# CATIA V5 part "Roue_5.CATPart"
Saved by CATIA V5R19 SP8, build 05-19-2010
Part number: Roue_5
Nomenclature: 70_R5
Bounding box of the stored display mesh (mm): x -12.982 to 12.982, y -12.982 to 12.982, z 0 to 2
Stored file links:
  C:\Users\rphgr\Desktop\0_Tapis_TC520B_vitesse\Roue_5.CATPart
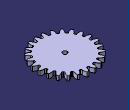
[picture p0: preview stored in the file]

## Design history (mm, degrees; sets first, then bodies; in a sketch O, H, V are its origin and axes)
External parameters (linked from other documents)
  External.Module = 1 mm
  External.Z = 24
  External.DiamPrimitif = 24 mm {= External.Module *External.Z}
  External.AnglePression = 20 deg
  External.x = 0
  External.DeportDenture = 0 mm {= External.x *External.Module}
  External.DiamBase = 22.5526 mm {= External.DiamPrimitif *cos(External.AnglePression )}
  External.DiamPied = 21.5 mm {= External.DiamPrimitif -2.5*External.Module +2*External.DeportDenture}
  External.DiamTete = 26 mm {= External.DiamPrimitif +2*External.Module +2*External.DeportDenture}
  External.PhiPrimitif = 0.854 deg {= atan((sin(External.ThetaPrimitif*1rad)-External.ThetaPrimitif*cos(External.ThetaPrimitif*1rad))/(cos(External.ThetaPrimitif*1rad)+External.ThetaPrimitif*sin(External.ThetaPrimitif*1rad)))}
  External.PhiTete = 3.0271 deg {= atan((sin(External.ThetaTete*1rad)-External.ThetaTete*cos(External.ThetaTete*1rad))/(cos(External.ThetaTete*1rad)+External.ThetaTete*sin(External.ThetaTete*1rad)))}
  External.PhiSymetrie = 3.75 deg {= 180*1 deg/(2*External.Z )}
  External.CongePied = 0.38 mm {= 0.38*External.Module}
  External.AlphaCopie = 15 deg {= 360*1 deg/External.Z}
  External.AlphaSymetrieCopie = 7.5 deg {= External.AlphaCopie /2}
  External.CoeffQualiteEngrenage = 7
  External.LargeurDenture = 2 mm
  External.ThetaPrimitif = 0.36397 {= sqrt(abs((External.DiamPrimitif*External.DiamPrimitif)/(External.DiamBase *External.DiamBase )-1))}
  External.ThetaTete = 0.573659 {= sqrt(abs((External.DiamTete*External.DiamTete)/(External.DiamBase *External.DiamBase )-1) )}
  External.Di = 23.2763 mm {= (External.DiamBase +External.DiamPrimitif )/2}
  External.Thetai = 0.255358 {= sqrt(abs((External.Di*External.Di)/(External.DiamBase*External.DiamBase)-1))}
  External.Phii = 0.3061 deg {= atan((sin(External.Thetai*1rad)-External.Thetai*cos(External.Thetai*1rad))/(cos(External.Thetai*1rad)+External.Thetai*sin(External.Thetai*1rad)))}
  External.Dj = 25 mm {= (External.DiamTete+External.DiamPrimitif)/2}
  External.Thetaj = 0.478344 {= sqrt(abs((External.Dj*External.Dj)/(External.DiamBase*External.DiamBase)-1))}
  External.Phij = 1.8433 deg {= atan((sin(External.Thetaj*1rad)-External.Thetaj*cos(External.Thetaj*1rad))/(cos(External.Thetaj*1rad)+External.Thetaj*sin(External.Thetaj*1rad)))}
  External.Dk = 22.9145 mm {= (External.Di+External.DiamBase)/2}
  External.Thetak = 0.179851 {= sqrt(abs((External.Dk*External.Dk)/(External.DiamBase*External.DiamBase)-1))}
  External.Phik = 0.109 deg {= atan((sin(External.Thetak*1rad)-External.Thetak*cos(External.Thetak*1rad))/(cos(External.Thetak*1rad)+External.Thetak*sin(External.Thetak*1rad)))}
  External.Dl = 23.6382 mm {= (External.DiamPrimitif+External.Di)/2}
  External.Thetal = 0.31398 {= sqrt(abs((External.Dl*External.Dl)/(External.DiamBase*External.DiamBase)-1))}
  External.Phil = 0.5585 deg {= atan((sin(External.Thetal*1rad)-External.Thetal*cos(External.Thetal*1rad))/(cos(External.Thetal*1rad)+External.Thetal*sin(External.Thetal*1rad)))}
  External.Dm = 24.5 mm {= (External.Dj+External.DiamPrimitif)/2}
  External.Thetam = 0.424444 {= sqrt(abs((External.Dm*External.Dm)/(External.DiamBase*External.DiamBase)-1))}
  External.Phim = 1.3203 deg {= atan((sin(External.Thetam*1rad)-External.Thetam*cos(External.Thetam*1rad))/(cos(External.Thetam*1rad)+External.Thetam*sin(External.Thetam*1rad)))}
  External.Dn = 25.5 mm {= (External.DiamTete+External.Dj)/2}
  External.Thetan = 0.527691 {= sqrt(abs((External.Dn*External.Dn)/(External.DiamBase*External.DiamBase)-1))}
  External.Phin = 2.4143 deg {= atan((sin(External.Thetan*1rad)-External.Thetan*cos(External.Thetan*1rad))/(cos(External.Thetan*1rad)+External.Thetan*sin(External.Thetan*1rad)))}
  External.DiametreAlesage = 2 mm
Body1 (main body)
  Sketch1 on xy-plane, origin (0, 0, 0), H (1, 0, 0), V (0, 1, 0)
    construction circle A1 centre (0, 0) radius 12
    construction circle A2 centre (0, 0) radius 11.2763
    construction circle A3 centre (0, 0) radius 10.75
    construction circle A4 centre (0, 0) radius 13
    point P1 (11.2763, 0)
    construction line L1 (11.2763, 0) -> (0, 0)
    point P2 (11.9987, 0.1788)
    construction line L2 (11.9987, 0.1788) -> (0, 0)
    point P3 (12.9819, 0.6865)
    construction line L3 (12.9819, 0.6865) -> (0, 0)
    construction line L4 (11.2763, 0) -> (11.2763, 3.9367)
    point P4 (11.2763, 0)
    point P6 (10.554, 0.1788)
    construction line L5 (12.9819, 0.6865) -> (11.9987, 0.1788)
    point P7 (12.4903, 0.4327)
    point P8 (10.0624, 0.4327)
    spline S1 through (10.0624, 0.4327) (10.554, 0.1788) (11.2763, 0) (11.4572, 0.0218) (11.638, 0.0622) (11.8185, 0.1152) (11.9987, 0.1788) (12.2467, 0.2823) (12.4935, 0.4021) (12.7387, 0.5371) (12.9819, 0.6865)
    construction line L6 (0, 0) -> (5.2574, 0.4234)
    spline S2 through (10.0019, 1.1831) (10.4466, 1.5123) (11.131, 1.8044) (11.3131, 1.8118) (11.498, 1.8009) (11.6847, 1.7775) (11.8727, 1.7435) (12.1341, 1.6811) (12.3969, 1.6023) (12.6605, 1.5083) (12.9244, 1.3997)
    arc A5 centre (11.1236, -0.3788) radius 0.38 from (11.147, 0.0005) to (10.7438, -0.3659) ccw
    point P11 (10.7438, -0.3659)
    arc A6 centre (0, 0) radius 13 from (12.9819, 0.6865) to (12.9244, 1.3997) ccw
    point P13 (12.9244, 1.3997)
    arc A7 centre (10.9196, 2.1539) radius 0.38 from (10.5468, 2.0804) to (11.0034, 1.7833) ccw
    point P15 (10.5468, 2.0804)
    construction line L7 (0, 0) -> (4.188, 0.8981)
    construction line L8 (0, 0) -> (5.1193, -0.259)
    point P19 (10.511, 2.2541)
    arc A8 centre (0, 0) radius 10.75 from (10.5468, 2.0804) to (10.511, 2.2541) ccw
    point P20 (10.7363, -0.5431)
    arc A9 centre (0, 0) radius 10.75 from (10.7363, -0.5431) to (10.7438, -0.3659) ccw
    line L9 (10.511, 2.2541) -> (0, 0)
    line L10 (10.7363, -0.5431) -> (0, 0)
    construction circle A10 centre (0, 0) radius 11.6382
    construction line L11 (0, 0) -> (2.5698, 0.0137)
    point P22 (11.638, 0.0622)
    construction circle A11 centre (0, 0) radius 12.5
    construction line L12 (0, 0) -> (4.017, 0.1293)
    point P24 (12.4935, 0.4021)
    point P25 (12.4935, 0.4021)
    point P26 (12.3969, 1.6023)
    point P27 (11.498, 1.8009)
    construction circle A12 centre (0, 0) radius 11.4572
    construction line L13 (0, 0) -> (48.2618, 0.0918)
    point P29 (11.3131, 1.8118)
    construction line L14 (0, 0) -> (63.772, 5.1354)
    point P31 (11.4572, 0.0218)
    construction circle A13 centre (0, 0) radius 11.8191
    construction line L15 (0, 0) -> (57.3607, 0.5591)
    point P33 (11.8185, 0.1152)
    point P34 (11.6847, 1.7775)
    construction circle A14 centre (0, 0) radius 12.25
    construction line L16 (0, 0) -> (65.6933, 1.5141)
    point P36 (12.2467, 0.2823)
    point P37 (12.1341, 1.6811)
    construction circle A15 centre (0, 0) radius 12.75
    axis line L17 (0, 0) -> (59.2983, 2.5001)
    point P39 (12.6605, 1.5083)
    point P40 (12.7387, 0.5371)
    point P42 (10.0624, 0.4327)
    point P43 (10.554, 0.1788)
    point P44 (11.2763, 0)
    point P45 (11.9987, 0.1788)
    point P46 (12.9819, 0.6865)
    point P47 (12.9244, 1.3997)
    point P48 (10.0019, 1.1831)
    point P49 (11.8727, 1.7435)
    point P50 (11.131, 1.8044)
    point P51 (10.4466, 1.5123)
    point P52 (11.638, 0.0622)
    point P53 (12.4935, 0.4021)
    point P54 (11.498, 1.8009)
    point P55 (12.3969, 1.6023)
    point P56 (11.4572, 0.0218)
    point P57 (11.3131, 1.8118)
    point P58 (11.8185, 0.1152)
    point P59 (11.6847, 1.7775)
    point P60 (12.2467, 0.2823)
    point P61 (12.1341, 1.6811)
    point P62 (12.7387, 0.5371)
    point P63 (12.6605, 1.5083)
    radius A1 = 12 {= External.DiamPrimitif /2}
    radius A2 = 11.2763 {= External.DiamBase /2}
    radius A3 = 10.75 {= External.DiamPied /2}
    radius A4 = 13 {= External.DiamTete /2}
    angle L2 L1 = 0.854 {= External.PhiPrimitif}
    angle L3 L1 = 3.0271 {= External.PhiTete}
    angle L4 L1 = 90
    radius A5 = 0.38 {= External.CongePied}
    radius A7 = 0.38 {= External.CongePied}
    angle L7 L6 = 7.5 {= External.AlphaSymetrieCopie}
    angle L2 L6 = 3.75 {= External.PhiSymetrie}
    radius A10 = 11.6382 {= External.Di /2}
    angle L11 L1 = 0.3061 {= External.Phii}
    radius A11 = 12.5 {= External.Dj /2}
    angle L12 L1 = 1.8433 {= External.Phij}
    radius A12 = 11.4572 {= External.Dk/2}
    angle L13 L1 = 0.109 {= External.Phik}
    angle L14 L2 = 3.75 {= External.PhiSymetrie}
    radius A13 = 11.8191 {= External.Dl /2}
    angle L15 L1 = 0.5585 {= External.Phil}
    radius A14 = 12.25 {= External.Dm /2}
    angle L16 L1 = 1.3203 {= External.Phim}
    radius A15 = 12.75 {= External.Dn/2}
    angle L17 L1 = 2.4143 {= External.Phin}
    coincidence: P1 A2, P1 H, P2 A1, P3 A4, P4 A2, P7 L5, P42 P8, P43 P6, P44 P1, P45 L5, P45 L2, P46 L5, P46 L3, P11 A3, P47 P13, P15 A3, P19 L7, P19 A3, P20 L8, P20 A3, P3 P46, P22 L11, P22 A10, P52 P22, P24 L12, P24 A11, P53 P24, P25 P53, P54 P27, P55 P26, P31 L13, P31 A12, P56 P31, P57 P29, P33 L15, P33 A13, P58 P33, P59 P34, P36 L16, P36 A14, P60 P36, P61 P37, P40 L17, P40 A15, P62 P40, P63 P39, O L9, O L10
    horizontal: L1 H
    tangency: L4 A2, A5 A3, A5 S1, A7 A3, A7 S2, A8 A5, A9 A5
    symmetry: P6 P2 L4, P8 P7 L4, P46 P47 L6, P42 P48 L6, P45 P49 L6, P44 P50 L6, P43 P51 L6, L8 L7 L6, P26 P25 L6, P27 P22 L6, P29 P31 L14, P34 P33 L14, P37 P36 L14, P39 P40 L14
    midpoint: P7 L5
    parallelism: L9 L7, L10 L8
    concentricity: A10 A2, A11 A1
  Pad1: profile Sketch1, direction (0, 0, 1), length 2 {= External.LargeurDenture}
  CircPattern1 "Roue Dentée": of Pad1, instances 24 {= External.Z}, angular step 15 {= External.AlphaCopie}, axis from Z axis
  Body2
    Sketch2 on xy-plane, origin (0, 0, 0), H (1, 0, 0), V (0, 1, 0)
      circle A1 centre (0, 0) radius 1
      radius A1 = 1 {= External.DiametreAlesage /2}
    Pad2: profile Sketch2, direction (0, 0, 1), length 4 {= 2*External.LargeurDenture}
  Remove1: tool Body2
  Sketch3 on face of CircPattern1, origin (0, 0, 0), H (1, 0, 0), V (0, -1, 0)
    circle A1 centre (0, 0) radius 2.5
    circle A2 centre (0, 0) radius 9.5
    radius A2 = 9.5
    radius A1 = 2.5
  Pocket1: profile Sketch3, direction (0, 0, 1), length 0.7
